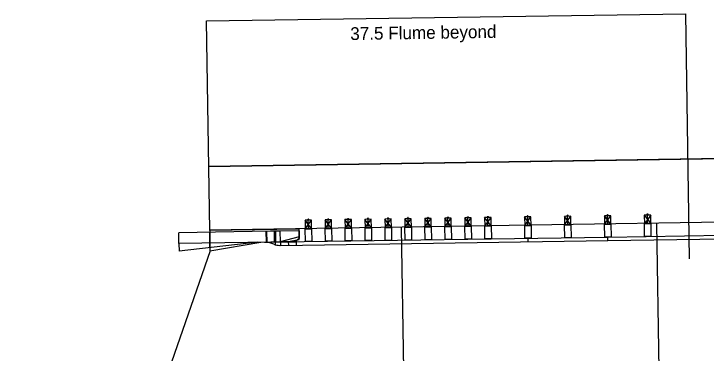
# Model space of a CAD drawing. Extents: x 17498307 to 17498862, y 7167523 to 7167641.
# Drawn here: x 17498673.6 to 17498727.8, y 7167598.2 to 7167624.7 of the extents above; entities that cross this region are included whole.
import ezdxf

# ---------------------------------------------------------------- set-up
doc = ezdxf.new("R2010")
doc.units = 0
for name, color, linetype in [('_CIVIL_CONSTRUCTION', 7, 'Continuous'), ('BridgeSuperStructure', 7, 'Continuous'), ('Default', 7, 'Continuous'), ('Draft_DNC', 7, 'Continuous'), ('dsnCellElements', 7, 'Continuous'), ('TL_ForeSlopeBarnRoof', 7, 'Continuous')]:
    doc.layers.add(name, color=color, linetype=linetype)

msp = doc.modelspace()

# ---------------------------------------------------------------- linework, layer by layer
at = {"layer": '_CIVIL_CONSTRUCTION'}
for p, q in [((17498761.322, 7167608.893), (17498688.968, 7167607.783)), ((17498723.964, 7167608.272), (17498724.669, 7167561.067)), ((17498703.967, 7167607.973), (17498704.671, 7167560.765)), ((17498688.995, 7167606.167), (17498673.635, 7167561.932))]:
    msp.add_line(p, q, dxfattribs=at)
at = {"layer": 'BridgeSuperStructure'}
msp.add_line((17498686.575, 7167606.13), (17498686.576, 7167606.13), dxfattribs=at)
at = {"layer": 'Default'}
msp.add_lwpolyline([(17498688.992, 7167606.166), (17498692.982, 7167606.851), (17498694.982, 7167606.881), (17498695.979, 7167607.062), (17498695.967, 7167607.854), (17498688.968, 7167607.749)], close=True, dxfattribs=at)
at = {"layer": 'Draft_DNC'}
for p, q in [((17498688.723, 7167624.164), (17498726.216, 7167624.723)), ((17498726.216, 7167624.723), (17498726.502, 7167605.534)), ((17498688.968, 7167607.749), (17498688.723, 7167624.164)), ((17498761.147, 7167613.891), (17498688.891, 7167612.783))]:
    msp.add_line(p, q, dxfattribs=at)
at = {"layer": 'dsnCellElements'}
for p, q in [((17498707.631, 7167608.811), (17498707.611, 7167608.81)), ((17498707.612, 7167608.781), (17498707.611, 7167608.81)), ((17498707.632, 7167608.781), (17498707.631, 7167608.811)), ((17498709.224, 7167608.805), (17498709.144, 7167608.804)), ((17498709.144, 7167608.766), (17498709.144, 7167608.804)), ((17498709.16, 7167608.766), (17498709.16, 7167608.804)), ((17498709.174, 7167608.804), (17498709.173, 7167608.834)), ((17498709.193, 7167608.834), (17498709.173, 7167608.834)), ((17498709.194, 7167608.804), (17498709.193, 7167608.834)), ((17498709.208, 7167608.767), (17498709.208, 7167608.805)), ((17498709.224, 7167608.767), (17498709.224, 7167608.805)), ((17498710.786, 7167608.828), (17498710.706, 7167608.827)), ((17498710.707, 7167608.79), (17498710.706, 7167608.827)), ((17498710.723, 7167608.79), (17498710.722, 7167608.827)), ((17498710.736, 7167608.827), (17498710.736, 7167608.857)), ((17498710.756, 7167608.857), (17498710.736, 7167608.857)), ((17498710.756, 7167608.828), (17498710.756, 7167608.857)), ((17498710.771, 7167608.791), (17498710.77, 7167608.828)), ((17498710.787, 7167608.791), (17498710.786, 7167608.828)), ((17498714.122, 7167608.824), (17498713.622, 7167608.817)), ((17498714.132, 7167608.157), (17498713.622, 7167608.817)), ((17498713.632, 7167608.15), (17498714.122, 7167608.824)), ((17498713.951, 7167608.838), (17498713.791, 7167608.836)), ((17498713.792, 7167608.819), (17498713.791, 7167608.836)), ((17498713.911, 7167608.875), (17498713.831, 7167608.874)), ((17498713.831, 7167608.836), (17498713.831, 7167608.874)), ((17498713.847, 7167608.836), (17498713.847, 7167608.874)), ((17498713.861, 7167608.874), (17498713.86, 7167608.904)), ((17498713.88, 7167608.904), (17498713.86, 7167608.904)), ((17498713.882, 7167608.154), (17498713.872, 7167608.82)), ((17498713.881, 7167608.874), (17498713.88, 7167608.904)), ((17498713.895, 7167608.837), (17498713.895, 7167608.875)), ((17498713.911, 7167608.837), (17498713.911, 7167608.875)), ((17498713.952, 7167608.821), (17498713.951, 7167608.838)), ((17498717.246, 7167608.871), (17498716.746, 7167608.863)), ((17498717.256, 7167608.204), (17498716.746, 7167608.863)), ((17498716.756, 7167608.197), (17498717.246, 7167608.871)), ((17498717.076, 7167608.885), (17498716.916, 7167608.882)), ((17498716.916, 7167608.866), (17498716.916, 7167608.882)), ((17498717.035, 7167608.921), (17498716.956, 7167608.92)), ((17498716.956, 7167608.883), (17498716.956, 7167608.92)), ((17498716.972, 7167608.883), (17498716.972, 7167608.92)), ((17498716.986, 7167608.921), (17498716.985, 7167608.95)), ((17498717.005, 7167608.95), (17498716.985, 7167608.95)), ((17498717.006, 7167608.2), (17498716.996, 7167608.867)), ((17498717.005, 7167608.921), (17498717.005, 7167608.95)), ((17498717.02, 7167608.884), (17498717.019, 7167608.921)), ((17498717.036, 7167608.884), (17498717.035, 7167608.921)), ((17498717.076, 7167608.868), (17498717.076, 7167608.885)), ((17498720.371, 7167608.917), (17498719.871, 7167608.91)), ((17498720.381, 7167608.251), (17498719.871, 7167608.91)), ((17498719.881, 7167608.243), (17498720.371, 7167608.917)), ((17498720.201, 7167608.931), (17498720.041, 7167608.929)), ((17498720.041, 7167608.912), (17498720.041, 7167608.929)), ((17498720.16, 7167608.968), (17498720.08, 7167608.967)), ((17498720.081, 7167608.93), (17498720.08, 7167608.967)), ((17498720.097, 7167608.93), (17498720.096, 7167608.967)), ((17498720.11, 7167608.967), (17498720.11, 7167608.997)), ((17498720.13, 7167608.997), (17498720.11, 7167608.997)), ((17498720.131, 7167608.247), (17498720.121, 7167608.914)), ((17498720.13, 7167608.968), (17498720.13, 7167608.997)), ((17498720.145, 7167608.93), (17498720.144, 7167608.968)), ((17498720.161, 7167608.931), (17498720.16, 7167608.968)), ((17498720.201, 7167608.915), (17498720.201, 7167608.931)), ((17498722.996, 7167608.956), (17498723.506, 7167608.297)), ((17498723.496, 7167608.964), (17498723.006, 7167608.29)), ((17498723.244, 7167609.057), (17498723.244, 7167609.064)), ((17498723.256, 7167608.293), (17498723.246, 7167608.96)), ((17498696.936, 7167608.567), (17498696.436, 7167608.56)), ((17498696.946, 7167607.901), (17498696.436, 7167608.56)), ((17498696.446, 7167607.893), (17498696.936, 7167608.567)), ((17498696.766, 7167608.581), (17498696.606, 7167608.579)), ((17498696.606, 7167608.563), (17498696.606, 7167608.579)), ((17498696.725, 7167608.618), (17498696.645, 7167608.617)), ((17498696.646, 7167608.58), (17498696.645, 7167608.617)), ((17498696.662, 7167608.58), (17498696.661, 7167608.617)), ((17498696.675, 7167608.618), (17498696.675, 7167608.647)), ((17498696.695, 7167608.647), (17498696.675, 7167608.647)), ((17498696.696, 7167607.897), (17498696.686, 7167608.564)), ((17498696.695, 7167608.618), (17498696.695, 7167608.647)), ((17498696.71, 7167608.581), (17498696.709, 7167608.618)), ((17498696.726, 7167608.581), (17498696.725, 7167608.618)), ((17498696.766, 7167608.565), (17498696.766, 7167608.581)), ((17498698.498, 7167608.591), (17498697.998, 7167608.583)), ((17498698.508, 7167607.924), (17498697.998, 7167608.583)), ((17498698.008, 7167607.917), (17498698.498, 7167608.591)), ((17498698.328, 7167608.605), (17498698.168, 7167608.602)), ((17498698.168, 7167608.586), (17498698.168, 7167608.602)), ((17498698.288, 7167608.642), (17498698.208, 7167608.64)), ((17498698.208, 7167608.603), (17498698.208, 7167608.64)), ((17498698.224, 7167608.603), (17498698.224, 7167608.641)), ((17498698.257, 7167608.671), (17498698.237, 7167608.67)), ((17498698.238, 7167608.641), (17498698.237, 7167608.67)), ((17498698.258, 7167607.921), (17498698.248, 7167608.587)), ((17498698.258, 7167608.641), (17498698.257, 7167608.671)), ((17498698.272, 7167608.604), (17498698.272, 7167608.641)), ((17498698.288, 7167608.604), (17498698.288, 7167608.642)), ((17498698.328, 7167608.588), (17498698.328, 7167608.605)), ((17498700.061, 7167608.614), (17498699.561, 7167608.607)), ((17498700.071, 7167607.948), (17498699.561, 7167608.607)), ((17498699.571, 7167607.94), (17498700.061, 7167608.614)), ((17498699.891, 7167608.628), (17498699.731, 7167608.626)), ((17498699.731, 7167608.609), (17498699.731, 7167608.626)), ((17498699.85, 7167608.665), (17498699.77, 7167608.664)), ((17498699.771, 7167608.626), (17498699.77, 7167608.664)), ((17498699.787, 7167608.627), (17498699.786, 7167608.664)), ((17498699.8, 7167608.664), (17498699.8, 7167608.694)), ((17498699.82, 7167608.694), (17498699.8, 7167608.694)), ((17498699.821, 7167607.944), (17498699.811, 7167608.61)), ((17498699.82, 7167608.664), (17498699.82, 7167608.694)), ((17498699.835, 7167608.627), (17498699.834, 7167608.665)), ((17498699.851, 7167608.628), (17498699.85, 7167608.665)), ((17498699.891, 7167608.612), (17498699.891, 7167608.628)), ((17498701.623, 7167608.637), (17498701.123, 7167608.63)), ((17498701.633, 7167607.971), (17498701.123, 7167608.63)), ((17498701.133, 7167607.963), (17498701.623, 7167608.637)), ((17498701.453, 7167608.651), (17498701.293, 7167608.649)), ((17498701.293, 7167608.633), (17498701.293, 7167608.649)), ((17498701.412, 7167608.688), (17498701.332, 7167608.687)), ((17498701.333, 7167608.65), (17498701.332, 7167608.687)), ((17498701.349, 7167608.65), (17498701.348, 7167608.687)), ((17498701.362, 7167608.687), (17498701.362, 7167608.717)), ((17498701.382, 7167608.717), (17498701.362, 7167608.717)), ((17498701.383, 7167607.967), (17498701.373, 7167608.634)), ((17498701.382, 7167608.688), (17498701.382, 7167608.717)), ((17498701.397, 7167608.651), (17498701.396, 7167608.688)), ((17498701.413, 7167608.651), (17498701.412, 7167608.688)), ((17498701.453, 7167608.635), (17498701.453, 7167608.651)), ((17498703.185, 7167608.661), (17498702.685, 7167608.653)), ((17498703.195, 7167607.994), (17498702.685, 7167608.653)), ((17498702.695, 7167607.987), (17498703.185, 7167608.661)), ((17498703.015, 7167608.675), (17498702.855, 7167608.672)), ((17498702.855, 7167608.656), (17498702.855, 7167608.672)), ((17498702.975, 7167608.712), (17498702.895, 7167608.71)), ((17498702.895, 7167608.673), (17498702.895, 7167608.71)), ((17498702.911, 7167608.673), (17498702.911, 7167608.711)), ((17498702.944, 7167608.741), (17498702.924, 7167608.74)), ((17498702.925, 7167608.711), (17498702.924, 7167608.74)), ((17498702.945, 7167607.99), (17498702.935, 7167608.657)), ((17498702.945, 7167608.711), (17498702.944, 7167608.741)), ((17498702.959, 7167608.674), (17498702.959, 7167608.711)), ((17498702.975, 7167608.674), (17498702.975, 7167608.712)), ((17498703.015, 7167608.658), (17498703.015, 7167608.675)), ((17498704.748, 7167608.684), (17498704.248, 7167608.677)), ((17498704.758, 7167608.018), (17498704.248, 7167608.677)), ((17498704.258, 7167608.01), (17498704.748, 7167608.684)), ((17498704.577, 7167608.698), (17498704.417, 7167608.696)), ((17498704.418, 7167608.679), (17498704.417, 7167608.696)), ((17498704.537, 7167608.735), (17498704.457, 7167608.734)), ((17498704.457, 7167608.696), (17498704.457, 7167608.734)), ((17498704.473, 7167608.697), (17498704.473, 7167608.734)), ((17498704.487, 7167608.734), (17498704.486, 7167608.764)), ((17498704.506, 7167608.764), (17498704.486, 7167608.764)), ((17498704.508, 7167608.014), (17498704.498, 7167608.68)), ((17498704.507, 7167608.734), (17498704.506, 7167608.764)), ((17498704.521, 7167608.697), (17498704.521, 7167608.735)), ((17498704.537, 7167608.697), (17498704.537, 7167608.735)), ((17498704.578, 7167608.682), (17498704.577, 7167608.698)), ((17498706.31, 7167608.707), (17498705.81, 7167608.7)), ((17498706.32, 7167608.041), (17498705.81, 7167608.7)), ((17498705.82, 7167608.033), (17498706.31, 7167608.707)), ((17498706.14, 7167608.721), (17498705.98, 7167608.719)), ((17498705.98, 7167608.702), (17498705.98, 7167608.719)), ((17498706.099, 7167608.758), (17498706.019, 7167608.757)), ((17498706.02, 7167608.72), (17498706.019, 7167608.757)), ((17498706.036, 7167608.72), (17498706.035, 7167608.757)), ((17498706.049, 7167608.757), (17498706.049, 7167608.787)), ((17498706.069, 7167608.787), (17498706.049, 7167608.787)), ((17498706.07, 7167608.037), (17498706.06, 7167608.704)), ((17498706.069, 7167608.758), (17498706.069, 7167608.787)), ((17498706.084, 7167608.721), (17498706.083, 7167608.758)), ((17498706.1, 7167608.721), (17498706.099, 7167608.758)), ((17498706.14, 7167608.705), (17498706.14, 7167608.721)), ((17498707.872, 7167608.731), (17498707.372, 7167608.723)), ((17498707.882, 7167608.064), (17498707.372, 7167608.723)), ((17498707.382, 7167608.057), (17498707.872, 7167608.731)), ((17498707.702, 7167608.745), (17498707.542, 7167608.742)), ((17498707.542, 7167608.726), (17498707.542, 7167608.742)), ((17498707.662, 7167608.782), (17498707.582, 7167608.78)), ((17498707.582, 7167608.743), (17498707.582, 7167608.78)), ((17498707.598, 7167608.743), (17498707.598, 7167608.781)), ((17498707.632, 7167608.06), (17498707.622, 7167608.727)), ((17498707.646, 7167608.744), (17498707.646, 7167608.781)), ((17498707.662, 7167608.744), (17498707.662, 7167608.782)), ((17498707.702, 7167608.728), (17498707.702, 7167608.745)), ((17498709.435, 7167608.754), (17498708.935, 7167608.747)), ((17498709.445, 7167608.088), (17498708.935, 7167608.747)), ((17498708.945, 7167608.08), (17498709.435, 7167608.754)), ((17498709.264, 7167608.768), (17498709.104, 7167608.766)), ((17498709.105, 7167608.749), (17498709.104, 7167608.766)), ((17498709.195, 7167608.084), (17498709.185, 7167608.75)), ((17498709.265, 7167608.752), (17498709.264, 7167608.768)), ((17498710.997, 7167608.777), (17498710.497, 7167608.77)), ((17498711.007, 7167608.111), (17498710.497, 7167608.77)), ((17498710.507, 7167608.103), (17498710.997, 7167608.777)), ((17498710.827, 7167608.791), (17498710.667, 7167608.789)), ((17498710.667, 7167608.772), (17498710.667, 7167608.789)), ((17498710.757, 7167608.107), (17498710.747, 7167608.774)), ((17498710.827, 7167608.775), (17498710.827, 7167608.791)), ((17498723.006, 7167608.29), (17498723.506, 7167608.297)), ((17498723.021, 7167607.289), (17498723.006, 7167608.29)), ((17498723.506, 7167608.297), (17498723.521, 7167607.296)), ((17498695.969, 7167607.729), (17498694.47, 7167607.706)), ((17498695.969, 7167607.729), (17498695.978, 7167607.135)), ((17498696.446, 7167607.893), (17498696.946, 7167607.901)), ((17498696.461, 7167606.894), (17498696.446, 7167607.893)), ((17498696.946, 7167607.901), (17498696.961, 7167606.902)), ((17498698.009, 7167607.917), (17498698.508, 7167607.924)), ((17498698.024, 7167606.917), (17498698.009, 7167607.917)), ((17498698.508, 7167607.924), (17498698.523, 7167606.925)), ((17498699.571, 7167607.94), (17498700.071, 7167607.948)), ((17498699.586, 7167606.941), (17498699.571, 7167607.94)), ((17498700.071, 7167607.948), (17498700.086, 7167606.948)), ((17498701.133, 7167607.963), (17498701.633, 7167607.971)), ((17498701.148, 7167606.964), (17498701.133, 7167607.963)), ((17498701.633, 7167607.971), (17498701.648, 7167606.972)), ((17498702.696, 7167607.987), (17498703.195, 7167607.994)), ((17498702.711, 7167606.987), (17498702.696, 7167607.987)), ((17498703.195, 7167607.994), (17498703.21, 7167606.995)), ((17498704.258, 7167608.01), (17498704.758, 7167608.018)), ((17498704.273, 7167607.011), (17498704.258, 7167608.01)), ((17498704.758, 7167608.018), (17498704.773, 7167607.018)), ((17498705.82, 7167608.033), (17498706.32, 7167608.041)), ((17498705.835, 7167607.034), (17498705.82, 7167608.033)), ((17498706.32, 7167608.041), (17498706.335, 7167607.041)), ((17498707.383, 7167608.057), (17498707.882, 7167608.064)), ((17498707.383, 7167608.057), (17498707.882, 7167608.064)), ((17498707.398, 7167607.057), (17498707.383, 7167608.057)), ((17498707.398, 7167607.057), (17498707.383, 7167608.057)), ((17498707.882, 7167608.064), (17498707.897, 7167607.065)), ((17498707.882, 7167608.064), (17498707.897, 7167607.065)), ((17498708.945, 7167608.08), (17498709.445, 7167608.088)), ((17498708.96, 7167607.081), (17498708.945, 7167608.08)), ((17498709.445, 7167608.088), (17498709.46, 7167607.088)), ((17498710.507, 7167608.103), (17498711.007, 7167608.111)), ((17498710.522, 7167607.104), (17498710.507, 7167608.103)), ((17498711.007, 7167608.111), (17498711.022, 7167607.111)), ((17498713.632, 7167608.15), (17498714.132, 7167608.157)), ((17498713.647, 7167607.151), (17498713.632, 7167608.15)), ((17498714.132, 7167608.157), (17498714.147, 7167607.158)), ((17498716.757, 7167608.197), (17498717.256, 7167608.204)), ((17498716.771, 7167607.197), (17498716.757, 7167608.197)), ((17498717.256, 7167608.204), (17498717.271, 7167607.205)), ((17498719.881, 7167608.243), (17498720.381, 7167608.251)), ((17498719.896, 7167607.244), (17498719.881, 7167608.243)), ((17498720.381, 7167608.251), (17498720.396, 7167607.251)), ((17498693.74, 7167607.696), (17498686.554, 7167607.588)), ((17498686.566, 7167606.744), (17498686.554, 7167607.588)), ((17498688.988, 7167606.407), (17498688.97, 7167607.624)), ((17498693.365, 7167607.69), (17498693.378, 7167606.846)), ((17498693.408, 7167607.638), (17498693.42, 7167606.82)), ((17498693.461, 7167606.847), (17498693.449, 7167607.691)), ((17498694.47, 7167607.706), (17498693.74, 7167607.696)), ((17498694.045, 7167606.856), (17498694.032, 7167607.7)), ((17498694.074, 7167607.648), (17498694.089, 7167606.646)), ((17498694.115, 7167607.701), (17498694.128, 7167606.857)), ((17498694.47, 7167607.706), (17498694.482, 7167606.863)), ((17498695.976, 7167607.26), (17498694.482, 7167606.863)), ((17498694.544, 7167606.863), (17498720.146, 7167607.246)), ((17498717.271, 7167607.205), (17498716.771, 7167607.197)), ((17498720.396, 7167607.251), (17498719.896, 7167607.244)), ((17498720.146, 7167607.246), (17498732.644, 7167607.433)), ((17498720.15, 7167606.975), (17498720.146, 7167607.246)), ((17498723.521, 7167607.296), (17498723.021, 7167607.289)), ((17498693.753, 7167606.852), (17498686.566, 7167606.744)), ((17498686.566, 7167606.744), (17498686.575, 7167606.13)), ((17498692.732, 7167606.836), (17498686.575, 7167606.13)), ((17498693.253, 7167606.844), (17498695.753, 7167606.882)), ((17498693.253, 7167606.844), (17498693.254, 7167606.818)), ((17498693.504, 7167606.822), (17498693.254, 7167606.818)), ((17498694.482, 7167606.863), (17498693.753, 7167606.852)), ((17498693.989, 7167606.678), (17498693.845, 7167606.731)), ((17498695.649, 7167606.88), (17498694.482, 7167606.863)), ((17498694.549, 7167606.593), (17498694.544, 7167606.863)), ((17498694.549, 7167606.593), (17498720.15, 7167606.975)), ((17498694.75, 7167606.866), (17498695.753, 7167606.881)), ((17498695.153, 7167606.602), (17498695.149, 7167606.873)), ((17498695.978, 7167607.135), (17498695.649, 7167606.88)), ((17498695.757, 7167606.611), (17498695.753, 7167606.882)), ((17498696.961, 7167606.902), (17498696.461, 7167606.894)), ((17498698.523, 7167606.925), (17498698.024, 7167606.917)), ((17498700.086, 7167606.948), (17498699.586, 7167606.941)), ((17498701.648, 7167606.972), (17498701.148, 7167606.964)), ((17498703.21, 7167606.995), (17498702.711, 7167606.987)), ((17498704.773, 7167607.018), (17498704.273, 7167607.011)), ((17498706.335, 7167607.041), (17498705.835, 7167607.034)), ((17498707.897, 7167607.065), (17498707.398, 7167607.057)), ((17498707.897, 7167607.065), (17498707.398, 7167607.057)), ((17498709.46, 7167607.088), (17498708.96, 7167607.081)), ((17498711.022, 7167607.111), (17498710.522, 7167607.104)), ((17498714.147, 7167607.158), (17498713.647, 7167607.151)), ((17498713.901, 7167606.882), (17498713.897, 7167607.153)), ((17498720.15, 7167606.975), (17498732.649, 7167607.162)), ((17498694.453, 7167606.591), (17498695.757, 7167606.611))]:
    msp.add_line(p, q, dxfattribs=at)
for points in [[(17498713.632, 7167608.15), (17498714.132, 7167608.157), (17498714.122, 7167608.824), (17498713.622, 7167608.817)], [(17498716.756, 7167608.197), (17498717.256, 7167608.204), (17498717.246, 7167608.871), (17498716.746, 7167608.863)], [(17498719.881, 7167608.243), (17498720.381, 7167608.251), (17498720.371, 7167608.917), (17498719.871, 7167608.91)], [(17498723.006, 7167608.29), (17498723.506, 7167608.297), (17498723.496, 7167608.964), (17498722.996, 7167608.956)], [(17498696.446, 7167607.893), (17498696.946, 7167607.901), (17498696.936, 7167608.567), (17498696.436, 7167608.56)], [(17498698.008, 7167607.917), (17498698.508, 7167607.924), (17498698.498, 7167608.591), (17498697.998, 7167608.583)], [(17498699.571, 7167607.94), (17498700.071, 7167607.948), (17498700.061, 7167608.614), (17498699.561, 7167608.607)], [(17498701.133, 7167607.963), (17498701.633, 7167607.971), (17498701.623, 7167608.637), (17498701.123, 7167608.63)], [(17498702.695, 7167607.987), (17498703.195, 7167607.994), (17498703.185, 7167608.661), (17498702.685, 7167608.653)], [(17498704.258, 7167608.01), (17498704.758, 7167608.018), (17498704.748, 7167608.684), (17498704.248, 7167608.677)], [(17498705.82, 7167608.033), (17498706.32, 7167608.041), (17498706.31, 7167608.707), (17498705.81, 7167608.7)], [(17498707.382, 7167608.057), (17498707.882, 7167608.064), (17498707.872, 7167608.731), (17498707.372, 7167608.723)], [(17498708.945, 7167608.08), (17498709.445, 7167608.088), (17498709.435, 7167608.754), (17498708.935, 7167608.747)], [(17498710.507, 7167608.103), (17498711.007, 7167608.111), (17498710.997, 7167608.777), (17498710.497, 7167608.77)]]:
    msp.add_lwpolyline(points, close=True, dxfattribs=at)
for points in [[(17498723.212, 7167608.96), (17498723.212, 7167609.003), (17498723.278, 7167609.004), (17498723.279, 7167608.961)], [(17498723.226, 7167609.003), (17498723.225, 7167609.057), (17498723.264, 7167609.058), (17498723.264, 7167609.003)]]:
    msp.add_lwpolyline(points, dxfattribs=at)
for centre, major_axis, start_param, end_param in [((17498693.311, 7167605.496), (-1.379, -0.021), 4.300427, 4.558114), ((17498694.509, 7167608.087), (1.541, 0.023), 4.353641, 4.661204)]:
    msp.add_ellipse(centre, major_axis=major_axis, ratio=0.97085, start_param=start_param, end_param=end_param, dxfattribs=at)
at = {"layer": 'TL_ForeSlopeBarnRoof'}
msp.add_lwpolyline([(17498688.891, 7167612.783), (17498761.147, 7167613.891), (17498808.165, 7167616.474), (17498808.165, 7167616.474), (17498828.401, 7167616.784)], dxfattribs=at)

# ---------------------------------------------------------------- texts
at = {"layer": 'Draft_DNC'}
msp.add_text('37.5 Flume beyond', height=1, rotation=0.8552, dxfattribs=at).set_placement((17498699.98, 7167622.671))

doc.saveas('drawing.dxf')
